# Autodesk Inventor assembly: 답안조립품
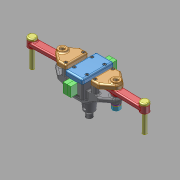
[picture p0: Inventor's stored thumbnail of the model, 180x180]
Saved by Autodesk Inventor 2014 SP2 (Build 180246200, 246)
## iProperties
Created: 2025-07
Part Number: 답안조립품
Document SubType Name: Assembly
Designer: Administrator
Author: Administrator
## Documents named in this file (11)
- C:\Users\Administrator\Desktop\750703V1008\답안조립품.iam
- C:\Users\Administrator\Desktop\750703V1008\본체.ipt
- C:\Users\Administrator\Desktop\750703V1008\가져온 구성요소\링크 커버\링크 커버.ipt
- C:\Users\Administrator\Desktop\750703V1008\가져온 구성요소\슬라이더 커버\슬라이더 커버.ipt
- C:\Users\Administrator\Desktop\750703V1008\가져온 구성요소\슬라이더\슬라이더.ipt
- C:\Users\Administrator\Desktop\750703V1008\가져온 구성요소\링크\링크.ipt
- C:\Users\Administrator\Desktop\750703V1008\가져온 구성요소\핀\핀.ipt
- C:\Users\Administrator\Desktop\750703V1008\가져온 구성요소\평 와셔 M8\평 와셔 M8.ipt
- C:\Users\Administrator\Desktop\750703V1008\가져온 구성요소\스프링 와셔 M8\스프링 와셔 M8.ipt
- C:\Users\Administrator\Desktop\750703V1008\가져온 구성요소\6각 너트 M8\6각 너트 M8.ipt
- C:\Users\Administrator\Desktop\750703V1008\가져온 구성요소\6각 구멍붙이 볼트 M3x10\6각 구멍붙이 볼트 M3x10.ipt
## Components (12 placed, 3 different names)
1. 핀:1
2. 핀:2
3. 6각 너트 M8:1
4. 6각 너트 M8:2
5. 6각 구멍붙이 볼트 M3x10:1
6. 6각 구멍붙이 볼트 M3x10:2
7. 6각 구멍붙이 볼트 M3x10:3
8. 6각 구멍붙이 볼트 M3x10:4
9. 6각 구멍붙이 볼트 M3x10:5
10. 6각 구멍붙이 볼트 M3x10:6
11. 6각 구멍붙이 볼트 M3x10:7
12. 6각 구멍붙이 볼트 M3x10:8
